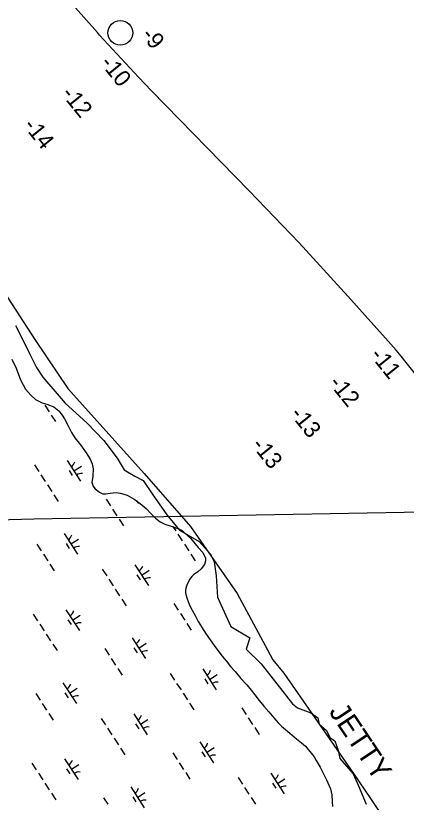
# Model space of a CAD drawing. Extents: x 3953924 to 3974542, y 193747 to 216192.
# Drawn here: x 3966178 to 3966966, y 199804 to 201392 of the extents above; entities that cross this region are included whole.
import ezdxf

# ---------------------------------------------------------------- set-up
doc = ezdxf.new("R2010")
doc.units = 0
for name, color, linetype in [('V-GRID-MAJR', 7, 'Continuous'), ('V-RIVR-EDGE', 7, 'Continuous'), ('V-RIVR-IDEN', 7, 'Continuous'), ('V-RIVR-JETY', 7, 'Continuous'), ('V-RIVR-MILE', 7, 'Continuous'), ('V-RIVR-RANG', 7, 'Continuous'), ('V-TOPO-MINR', 7, 'Continuous'), ('V-WETL-SWMP', 7, 'Continuous')]:
    doc.layers.add(name, color=color, linetype=linetype)

msp = doc.modelspace()

# ---------------------------------------------------------------- linework, layer by layer
at = {"layer": 'V-GRID-MAJR'}
msp.add_spline([(3963152.5, 200318.9), (3967932.3, 200408.2), (3973258, 200508.6), (3973424, 200511.7)], degree=3, dxfattribs=at)
at = {"layer": 'V-RIVR-EDGE'}
msp.add_lwpolyline([(3966177.6, 200766.1), (3966190.4, 200741.8), (3966205.8, 200709.8), (3966219.8, 200681.6), (3966232.6, 200662.4), (3966277.5, 200609.9), (3966321, 200570.2), (3966355.6, 200534.3), (3966382.5, 200498.5), (3966396.6, 200475.4), (3966418.3, 200462.6), (3966435, 200453.6), (3966452.9, 200426.7), (3966482.4, 200384.5), (3966508, 200353.7), (3966547.7, 200330.7), (3966570.7, 200305.1), (3966578.4, 200289.7), (3966582.3, 200261.5), (3966584.8, 200218), (3966611.7, 200159.1), (3966650.1, 200136), (3966642.5, 200113), (3966673.2, 200083.5), (3966735.9, 200002.8), (3966746.2, 199995.2), (3966773.1, 199984.9), (3966787.2, 199974.7), (3966789.7, 199961.9), (3966805.1, 199949.1), (3966811.5, 199935), (3966821.7, 199928.6), (3966828.1, 199909.4), (3966832, 199892.7), (3966858.9, 199862), (3966869.1, 199837.6), (3966884.5, 199800.5)], dxfattribs=at)
at = {"layer": 'V-RIVR-JETY'}
msp.add_lwpolyline([(3965387.4, 201766), (3965676.4, 201395.8), (3965795.6, 201267.6), (3965922, 201152), (3966044.8, 201002.1), (3966216.4, 200738.4), (3966283.2, 200639.1), (3966436.7, 200467.6), (3966530.6, 200361), (3966624.5, 200225.5), (3966685.9, 200111.8), (3966696.8, 200091.9), (3966718.4, 200064.8), (3966859.3, 199862.5), (3966893.6, 199812), (3967164.5, 199403.8), (3967289.1, 199197.9), (3967375.8, 199057.1), (3967522.1, 198887.3), (3967612.4, 198786.2), (3967746, 198636.3), (3967827.3, 198542.4), (3968004.3, 198338.3), (3968150.6, 198174)], dxfattribs=at)
at = {"layer": 'V-RIVR-MILE'}
msp.add_circle((3966388.9, 201357), 25, dxfattribs=at)
at = {"layer": 'V-TOPO-MINR'}
msp.add_lwpolyline([(3967082.6, 200545.4), (3966965.7, 200691.7), (3966955.5, 200704.3), (3966945.1, 200716.7), (3966934.5, 200729), (3966923.8, 200741.1), (3966848, 200825.5), (3966799, 200879.5), (3966749.5, 200933), (3966699.3, 200985.9), (3966648.7, 201038.4), (3966452, 201240), (3966425.4, 201267.6), (3966399, 201295.6), (3966372.9, 201323.8), (3966347.1, 201352.3), (3966342.6, 201357.4), (3966314.9, 201388.7), (3966287.3, 201420.2)], dxfattribs=at)
at = {"layer": 'V-WETL-SWMP'}
for p, q in [((3966170.2, 200698.8), (3966178.4, 200680)), ((3966178.4, 200680), (3966187.2, 200656.9)), ((3966187.2, 200656.9), (3966197.4, 200637.7)), ((3966197.4, 200637.7), (3966208, 200625.8)), ((3966208, 200625.8), (3966217.6, 200617.1)), ((3966217.6, 200617.1), (3966231.4, 200610.6)), ((3966231.4, 200610.6), (3966240.7, 200607.7)), ((3966236.3, 200605.9), (3966245, 200592.5)), ((3966240.7, 200607.7), (3966254.6, 200602.4)), ((3966254.6, 200602.4), (3966264.5, 200594.4)), ((3966249.4, 200585.8), (3966258.1, 200572.4)), ((3966264.5, 200594.4), (3966271.8, 200585.7)), ((3966271.8, 200585.7), (3966276.3, 200578.3)), ((3966276.3, 200578.3), (3966283.8, 200564.1)), ((3966283.8, 200564.1), (3966290.1, 200550.8)), ((3966290.1, 200550.8), (3966297.3, 200539.8)), ((3966297.3, 200539.8), (3966308.7, 200525.5)), ((3966308.7, 200525.5), (3966320, 200509.8)), ((3966320, 200509.8), (3966327.9, 200496.4)), ((3966281.4, 200494), (3966308.7, 200452.1)), ((3966327.9, 200496.4), (3966332, 200487)), ((3966215.6, 200485.1), (3966224.3, 200471.7)), ((3966285.3, 200473.9), (3966291.9, 200463.8)), ((3966295.1, 200473.1), (3966310.2, 200482.9)), ((3966332, 200487), (3966334.2, 200476.9)), ((3966334.2, 200476.9), (3966333.1, 200462.1)), ((3966228.7, 200465), (3966237.4, 200451.6)), ((3966333.1, 200462.1), (3966331.3, 200449.3)), ((3966241.8, 200444.9), (3966250.5, 200431.4)), ((3966331.3, 200449.3), (3966332.4, 200446.2)), ((3966332.4, 200446.2), (3966333.1, 200443.1)), ((3966333.1, 200443.1), (3966338.4, 200436.7)), ((3966338.4, 200436.7), (3966346.5, 200430)), ((3966346.5, 200430), (3966353.4, 200426.7)), ((3966353.4, 200426.7), (3966359.6, 200426.6)), ((3966359.6, 200426.6), (3966368.6, 200428.4)), ((3966368.6, 200428.4), (3966380.3, 200429.3)), ((3966380.3, 200429.3), (3966388.4, 200428)), ((3966388.4, 200428), (3966396.1, 200425.9)), ((3966254.9, 200424.7), (3966263.6, 200411.3)), ((3966360.1, 200415.7), (3966368.8, 200402.3)), ((3966396.1, 200425.9), (3966402.7, 200423.8)), ((3966402.7, 200423.8), (3966416.9, 200416.2)), ((3966416.9, 200416.2), (3966429.2, 200407.4)), ((3966421.7, 200412.8), (3966425.3, 200407.2)), ((3966373.2, 200395.6), (3966381.9, 200382.2)), ((3966429.2, 200407.4), (3966441.1, 200397.4)), ((3966440.6, 200397.8), (3966442.1, 200395.5)), ((3966441.1, 200397.4), (3966451.3, 200386.4)), ((3966451.3, 200386.4), (3966460.1, 200377.6)), ((3966386.3, 200375.5), (3966395, 200362.1)), ((3966460.1, 200377.6), (3966468.9, 200370.5)), ((3966468.9, 200370.5), (3966478.9, 200365.6)), ((3966478.9, 200365.6), (3966489.7, 200362.3)), ((3966489.7, 200362.3), (3966497.5, 200359.8)), ((3966495.1, 200360.6), (3966500.7, 200352.1)), ((3966497.5, 200359.8), (3966507.9, 200355.3)), ((3966507.9, 200355.3), (3966513.3, 200352.5)), ((3966513.3, 200352.5), (3966519, 200347.7)), ((3966519, 200347.7), (3966530.1, 200337)), ((3966275.5, 200346.7), (3966302.7, 200304.7)), ((3966289.1, 200325.7), (3966304.2, 200335.5)), ((3966505, 200345.4), (3966513.7, 200332)), ((3966530.1, 200337), (3966546, 200318.5)), ((3966220.7, 200325), (3966229.4, 200311.6)), ((3966279.4, 200326.5), (3966285.9, 200316.5)), ((3966518.1, 200325.3), (3966526.8, 200311.9)), ((3966546, 200318.5), (3966555.5, 200308.2)), ((3966233.8, 200304.9), (3966242.5, 200291.4)), ((3966531.2, 200305.2), (3966539.9, 200291.8)), ((3966555.5, 200308.2), (3966560.4, 200296.8)), ((3966246.9, 200284.7), (3966255.6, 200271.3)), ((3966418.3, 200283.7), (3966445.6, 200241.8)), ((3966558.6, 200284), (3966552.2, 200275.6)), ((3966561, 200291.3), (3966558.6, 200284)), ((3966560.4, 200296.8), (3966560.7, 200291.4)), ((3966560.7, 200291.4), (3966561, 200291.3)), ((3966352.5, 200274.8), (3966361.3, 200261.4)), ((3966432, 200262.7), (3966447.1, 200272.6)), ((3966545.1, 200269.5), (3966536.8, 200263.4)), ((3966552.2, 200275.6), (3966545.1, 200269.5)), ((3966365.6, 200254.6), (3966374.3, 200241.2)), ((3966422.2, 200263.6), (3966428.8, 200253.5)), ((3966528.4, 200253.9), (3966522.8, 200242.7)), ((3966532.8, 200260), (3966528.4, 200253.9)), ((3966536.8, 200263.4), (3966532.8, 200260)), ((3966520.7, 200236.2), (3966520.2, 200231.5)), ((3966522.8, 200242.7), (3966520.7, 200236.2)), ((3966378.7, 200234.5), (3966387.4, 200221.1)), ((3966520.2, 200231.5), (3966520.2, 200228)), ((3966520.2, 200228), (3966521.3, 200223.7)), ((3966521.3, 200223.7), (3966523.1, 200217.1)), ((3966391.8, 200214.4), (3966400.5, 200201)), ((3966497, 200205.4), (3966505.7, 200192)), ((3966523.1, 200217.1), (3966526.4, 200207.7)), ((3966526.4, 200207.7), (3966529.4, 200200.6)), ((3966278.9, 200192.9), (3966306.2, 200151)), ((3966529.4, 200200.6), (3966533.9, 200192)), ((3966533.9, 200192), (3966540.2, 200179.8)), ((3966213.1, 200184), (3966221.8, 200170.6)), ((3966282.8, 200172.8), (3966289.4, 200162.8)), ((3966292.6, 200172), (3966307.7, 200181.8)), ((3966510.1, 200185.3), (3966518.8, 200171.9)), ((3966540.2, 200179.8), (3966546.2, 200168.8)), ((3966226.2, 200163.9), (3966234.9, 200150.5)), ((3966523.2, 200165.2), (3966531.9, 200151.8)), ((3966546.2, 200168.8), (3966552.6, 200158.6)), ((3966552.6, 200158.6), (3966561.7, 200143.6)), ((3966239.3, 200143.8), (3966248, 200130.4)), ((3966561.7, 200143.6), (3966570, 200131.8)), ((3966412.4, 200136.3), (3966439.6, 200094.4)), ((3966426, 200115.4), (3966441.1, 200125.2)), ((3966570, 200131.8), (3966577.9, 200120.4)), ((3966252.4, 200123.7), (3966261.1, 200110.3)), ((3966357.6, 200114.7), (3966366.3, 200101.2)), ((3966416.3, 200116.2), (3966422.8, 200106.1)), ((3966577.9, 200120.4), (3966587.4, 200108.2)), ((3966370.7, 200094.5), (3966379.4, 200081.1)), ((3966587.4, 200108.2), (3966594.2, 200099.5)), ((3966594.2, 200099.5), (3966602.2, 200090)), ((3966602.2, 200090), (3966611.3, 200078.6)), ((3966611.3, 200078.6), (3966620.4, 200067.9)), ((3966383.8, 200074.4), (3966392.5, 200061)), ((3966489.4, 200064.4), (3966498.2, 200051)), ((3966555.2, 200073.4), (3966582.5, 200031.5)), ((3966568.9, 200052.4), (3966584, 200062.2)), ((3966620.4, 200067.9), (3966632.2, 200054.4)), ((3966273, 200045.6), (3966300.2, 200003.7)), ((3966559.1, 200053.2), (3966565.7, 200043.2)), ((3966632.2, 200054.4), (3966644, 200041.4)), ((3966286.6, 200024.6), (3966301.7, 200034.5)), ((3966502.5, 200044.3), (3966511.3, 200030.9)), ((3966644, 200041.4), (3966652.8, 200030.7)), ((3966652.8, 200030.7), (3966660.3, 200020.9)), ((3966218.2, 200023.9), (3966226.9, 200010.5)), ((3966276.9, 200025.5), (3966283.4, 200015.4)), ((3966515.6, 200024.2), (3966524.3, 200010.8)), ((3966660.3, 200020.9), (3966669.1, 200009.8)), ((3966231.3, 200003.8), (3966240, 199990.4)), ((3966528.7, 200004.1), (3966537.4, 199990.7)), ((3966669.1, 200009.8), (3966678.6, 199998.4)), ((3966678.6, 199998.4), (3966688.4, 199986.9)), ((3966244.4, 199983.7), (3966253.1, 199970.3)), ((3966415.8, 199982.6), (3966443.1, 199940.7)), ((3966633.9, 199995.1), (3966642.6, 199981.7)), ((3966688.4, 199986.9), (3966698.3, 199975)), ((3966350, 199973.7), (3966358.8, 199960.3)), ((3966429.5, 199961.7), (3966444.6, 199971.5)), ((3966647, 199975), (3966655.7, 199961.6)), ((3966698.3, 199975), (3966707.4, 199964.4)), ((3966363.1, 199953.6), (3966371.8, 199940.2)), ((3966419.7, 199962.5), (3966426.3, 199952.4)), ((3966660.1, 199954.9), (3966668.8, 199941.4)), ((3966707.4, 199964.4), (3966713.9, 199957.6)), ((3966713.9, 199957.6), (3966734.6, 199940.1)), ((3966734.6, 199940.1), (3966744.5, 199932.6)), ((3966376.2, 199933.5), (3966384.9, 199920.1)), ((3966549.3, 199926), (3966576.5, 199884.1)), ((3966744.5, 199932.6), (3966754.5, 199924.6)), ((3966754.5, 199924.6), (3966762.5, 199917.4)), ((3966389.3, 199913.4), (3966398, 199899.9)), ((3966494.5, 199904.3), (3966503.2, 199890.9)), ((3966553.2, 199905.9), (3966559.7, 199895.8)), ((3966562.9, 199905.1), (3966578, 199914.9)), ((3966762.5, 199917.4), (3966767.8, 199911.1)), ((3966767.8, 199911.1), (3966774.7, 199902.8)), ((3966774.7, 199902.8), (3966779.6, 199896.1)), ((3966276.4, 199891.9), (3966303.7, 199850)), ((3966779.6, 199896.1), (3966784.1, 199888.7)), ((3966784.1, 199888.7), (3966792, 199875.3)), ((3966210.6, 199883), (3966219.3, 199869.5)), ((3966280.3, 199871.7), (3966286.9, 199861.7)), ((3966290.1, 199870.9), (3966305.2, 199880.8)), ((3966507.6, 199884.2), (3966516.3, 199870.8)), ((3966792, 199875.3), (3966804.7, 199849.4)), ((3966223.7, 199862.8), (3966232.4, 199849.4)), ((3966520.7, 199864.1), (3966529.4, 199850.7)), ((3966692.2, 199863.1), (3966719.4, 199821.1)), ((3966236.8, 199842.7), (3966245.5, 199829.3)), ((3966626.3, 199854.1), (3966635.1, 199840.7)), ((3966696.1, 199842.9), (3966702.6, 199832.9)), ((3966705.8, 199842.1), (3966720.9, 199851.9)), ((3966804.7, 199849.4), (3966812.9, 199831.4)), ((3966409.9, 199835.3), (3966437.1, 199793.4)), ((3966423.5, 199814.3), (3966438.6, 199824.1)), ((3966639.4, 199834), (3966648.2, 199820.6)), ((3966812.9, 199831.4), (3966815.4, 199819.3)), ((3966249.9, 199822.6), (3966258.6, 199809.2)), ((3966355.1, 199813.6), (3966363.8, 199800.2)), ((3966413.8, 199815.1), (3966420.3, 199805.1)), ((3966652.5, 199813.9), (3966661.3, 199800.5)), ((3966815.4, 199819.3), (3966816.3, 199805.2)), ((3966816.3, 199805.2), (3966816.9, 199795.9))]:
    msp.add_line(p, q, dxfattribs=at)
for centre, start, end in [((3966280.2, 200496.3), 302.2901, 343.8338), ((3966310.3, 200450), 82.2901, 123.8337), ((3966274.2, 200349), 302.2901, 343.8338), ((3966304.4, 200302.7), 82.2901, 123.8337), ((3966417.1, 200286), 302.2901, 343.8338), ((3966447.2, 200239.7), 82.2901, 123.8337), ((3966277.7, 200195.3), 302.2901, 343.8338), ((3966307.8, 200149), 82.2901, 123.8337), ((3966411.1, 200138.7), 302.2901, 343.8338), ((3966441.3, 200092.4), 82.2901, 123.8337), ((3966554, 200075.7), 302.2901, 343.8338), ((3966584.2, 200029.4), 82.2901, 123.8337), ((3966271.7, 200047.9), 302.2901, 343.8338), ((3966301.9, 200001.6), 82.2901, 123.8337), ((3966414.6, 199985), 302.2901, 343.8338), ((3966444.8, 199938.7), 82.2901, 123.8337), ((3966548, 199928.3), 302.2901, 343.8338), ((3966275.2, 199894.2), 302.2901, 343.8338), ((3966578.2, 199882), 82.2901, 123.8337), ((3966305.3, 199847.9), 82.2901, 123.8337), ((3966690.9, 199865.4), 302.2901, 343.8338), ((3966408.6, 199837.6), 302.2901, 343.8338), ((3966721.1, 199819.1), 82.2901, 123.8337), ((3966438.8, 199791.3), 82.2901, 123.8337)]:
    msp.add_arc(centre, 17.6, start, end, dxfattribs=at)

# ---------------------------------------------------------------- texts
at = {"layer": 'V-RIVR-IDEN'}
msp.add_text('JETTY', height=42, rotation=303.8611, dxfattribs=at).set_placement((3966808.4, 199986.9))
at = {"layer": 'V-RIVR-RANG'}
for s, rotation, p in [('-9', 308.9396, (3966429.7, 201351.9)), ('-10', 308.9396, (3966346.8, 201295.4)), ('-12', 308.9396, (3966268.3, 201233.2)), ('-14', 308.9396, (3966191.6, 201169.2)), ('-11', 308.8107, (3966891.3, 200705.9)), ('-12', 308.8107, (3966808, 200649.6)), ('-13', 308.8107, (3966729.9, 200587.1)), ('-13', 308.8107, (3966652.1, 200524.5))]:
    msp.add_text(s, height=33.5, rotation=rotation, dxfattribs=at).set_placement(p)

doc.saveas('drawing.dxf')
